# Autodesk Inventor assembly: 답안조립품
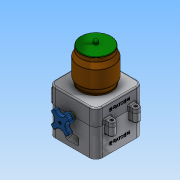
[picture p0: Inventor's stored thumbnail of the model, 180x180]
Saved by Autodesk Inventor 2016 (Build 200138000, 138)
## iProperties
Created: 2018-01
Part Number: 답안조립품
Material: 일반
Document SubType Name: Assembly
Designer: Administrator
Author: Administrator
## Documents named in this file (9)
- C:\Users\Administrator\Desktop\480107V1032\답안조립품.iam
- C:\Users\Administrator\Desktop\480107V1032\본체.ipt
- C:\Users\Administrator\Desktop\480107V1032\핸들축.ipt
- C:\Users\Administrator\Desktop\480107V1032\본체커버.ipt
- C:\Users\Administrator\Desktop\480107V1032\용기.ipt
- C:\Users\Administrator\Desktop\480107V1032\용기캡.ipt
- C:\Users\Administrator\Desktop\480107V1032\볼트 M4x12.ipt
- C:\Users\Administrator\Desktop\480107V1032\핸들.ipt
- C:\Users\Administrator\Desktop\480107V1032\볼트 M3x12.ipt
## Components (2 placed, 2 different names)
1. 핸들축:1 — 플러쉬:1
2. 핸들:1
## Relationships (1: Flush 1)
- 플러쉬:1 [Flush]: 핸들축:1
